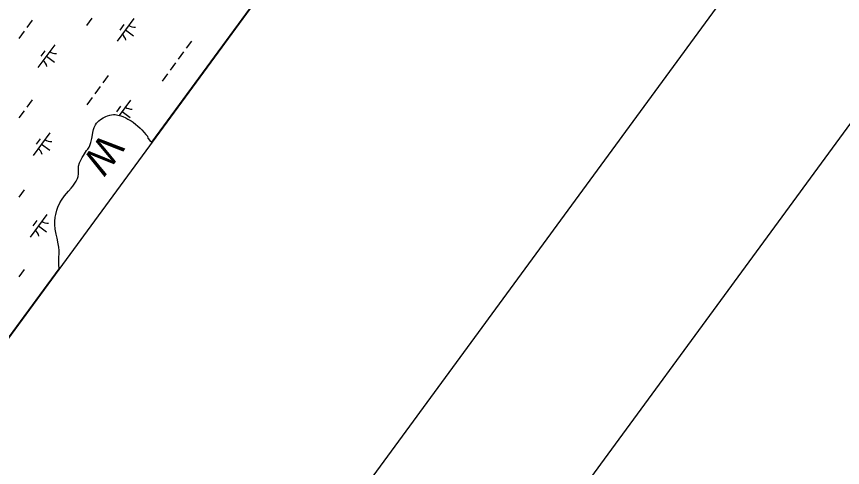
# Model space of a CAD drawing. Extents: x 3905714 to 3926767, y 183354 to 205755.
# Drawn here: x 3918098 to 3919561, y 188274 to 189073 of the extents above; entities that cross this region are included whole.
import ezdxf

# ---------------------------------------------------------------- set-up
doc = ezdxf.new("R2010")
doc.units = 0
for name, color, linetype in [('G-ANNO-NPLT', 7, 'Continuous'), ('V-ANNO-SYMB', 7, 'Continuous'), ('V-GRID-FRAM', 7, 'Continuous'), ('V-RIVR-IDEN', 7, 'Continuous'), ('V-TOPO-SHOR', 7, 'Continuous'), ('V-WETL-SWMP', 7, 'Continuous')]:
    doc.layers.add(name, color=color, linetype=linetype)

msp = doc.modelspace()

# ---------------------------------------------------------------- linework, layer by layer
at = {"layer": 'G-ANNO-NPLT'}
msp.add_lwpolyline([(3916784.5, 205519.9), (3905949.4, 190731), (3915696.7, 183589.7), (3926531.8, 198378.7)], close=True, dxfattribs=at)
at = {"layer": 'V-ANNO-SYMB'}
msp.add_lwpolyline([(3916223.9, 204226), (3906447.8, 190882.4), (3915690.8, 184110.5), (3925467, 197454.1), (3916223.9, 204226)], dxfattribs=at)
at = {"layer": 'V-GRID-FRAM'}
msp.add_lwpolyline([(3924287.8, 196971.1), (3915521.4, 185005.6), (3909313.3, 189695.8), (3918205.9, 201877.9), (3924287.8, 196971.1)], dxfattribs=at)
at = {"layer": 'V-TOPO-SHOR'}
msp.add_lwpolyline([(3918173.7, 188625.7), (3918173.1, 188633), (3918173.2, 188638), (3918173.6, 188646), (3918174, 188652.1), (3918174, 188658), (3918173.3, 188663.7), (3918172.4, 188670), (3918170.2, 188680.1), (3918168.8, 188686.8), (3918167, 188695.7), (3918166.4, 188704), (3918166.5, 188709.4), (3918167, 188717.3), (3918167.9, 188722), (3918169.9, 188729.7), (3918171.7, 188734.7), (3918175.2, 188742.4), (3918178.2, 188747.4), (3918183.2, 188755), (3918186.8, 188759.3), (3918190.2, 188763.3), (3918195.3, 188768.7), (3918198.2, 188772.2), (3918201.8, 188777.3), (3918204, 188780.7), (3918206.4, 188785.5), (3918207.3, 188788.9), (3918207.9, 188794.1), (3918208.3, 188799.8), (3918208.3, 188807.4), (3918210, 188813.4), (3918211.5, 188817), (3918214.8, 188822.6), (3918217, 188826.4), (3918220.8, 188832.2), (3918222.4, 188835.2), (3918224.5, 188837.7), (3918226.9, 188841.4), (3918228, 188844.2), (3918230.1, 188849.2), (3918231.8, 188856.7), (3918233.1, 188862.8), (3918233.8, 188866.9), (3918234.9, 188872.6), (3918235.9, 188876), (3918238.2, 188880.8), (3918240.3, 188883.6), (3918244.2, 188887.6), (3918247.1, 188890.3), (3918251.7, 188893.4), (3918256.3, 188895.6), (3918259.3, 188896.7), (3918263.8, 188897.9), (3918266.8, 188898.6), (3918270.1, 188899.1), (3918273.1, 188899), (3918277.9, 188897.8), (3918283.3, 188896.4), (3918286.8, 188895.3), (3918292.1, 188893), (3918295.8, 188891), (3918301.2, 188887.7), (3918304.9, 188885.4), (3918309.8, 188881.4), (3918312.9, 188878.8), (3918317.2, 188874.8), (3918320.1, 188871.7), (3918324.6, 188867), (3918327.6, 188863.6), (3918330.3, 188860.4), (3918331.2, 188857.2), (3918334.7, 188853.2), (3918337.9, 188849.9)], dxfattribs=at)
at = {"layer": 'V-WETL-SWMP'}
for p, q in [((3918337.9, 188849.9), (3919501.5, 190438.1)), ((3918126.3, 189066.2), (3918116.9, 189053.3)), ((3918231.7, 189069.5), (3918222.3, 189056.6)), ((3918305.9, 189069.2), (3918276.4, 189028.8)), ((3918288.5, 189058.4), (3918281.4, 189048.7)), ((3918291.2, 189049), (3918305.7, 189038.4)), ((3918112.1, 189046.8), (3918102.7, 189033.9)), ((3918166, 189022.6), (3918136.4, 188982.3)), ((3918408.5, 189029.3), (3918399, 189016.4)), ((3918148.5, 189011.9), (3918141.4, 189002.2)), ((3918394.3, 189009.9), (3918384.8, 188997)), ((3918151.2, 189002.5), (3918165.7, 188991.8)), ((3918380.1, 188990.5), (3918370.7, 188977.6)), ((3918260.5, 188967.9), (3918251.1, 188955)), ((3918365.9, 188971.2), (3918356.5, 188958.3)), ((3918246.3, 188948.5), (3918236.9, 188935.6)), ((3918126, 188925.1), (3918116.5, 188912.2)), ((3918232.1, 188929.2), (3918222.7, 188916.3)), ((3918300.2, 188924.3), (3918280.3, 188897.2)), ((3918111.8, 188905.8), (3918102.3, 188892.9)), ((3918282.7, 188913.6), (3918275.6, 188903.9)), ((3918285.4, 188904.2), (3918299.9, 188893.5)), ((3918244.2, 188887.6), (3918247.1, 188890.3)), ((3918247.1, 188890.3), (3918251.7, 188893.4)), ((3918251.7, 188893.4), (3918256.3, 188895.6)), ((3918256.3, 188895.6), (3918259.3, 188896.7)), ((3918259.3, 188896.7), (3918263.8, 188897.9)), ((3918263.8, 188897.9), (3918266.8, 188898.6)), ((3918266.8, 188898.6), (3918270.1, 188899.1)), ((3918270.1, 188899.1), (3918273.1, 188899)), ((3918273.1, 188899), (3918277.9, 188897.8)), ((3918277.9, 188897.8), (3918283.3, 188896.4)), ((3918283.3, 188896.4), (3918286.8, 188895.3)), ((3918286.8, 188895.3), (3918292.1, 188893)), ((3918292.1, 188893), (3918295.8, 188891)), ((3918295.8, 188891), (3918301.2, 188887.7)), ((3918301.2, 188887.7), (3918304.9, 188885.4)), ((3918234.9, 188872.6), (3918235.9, 188876)), ((3918235.9, 188876), (3918238.2, 188880.8)), ((3918238.2, 188880.8), (3918240.3, 188883.6)), ((3918240.3, 188883.6), (3918244.2, 188887.6)), ((3918304.9, 188885.4), (3918309.8, 188881.4)), ((3918309.8, 188881.4), (3918312.9, 188878.8)), ((3918312.9, 188878.8), (3918317.2, 188874.8)), ((3918317.2, 188874.8), (3918320.1, 188871.7)), ((3918157.6, 188866.7), (3918128.1, 188826.4)), ((3918231.8, 188856.7), (3918233.1, 188862.8)), ((3918233.1, 188862.8), (3918233.8, 188866.9)), ((3918233.8, 188866.9), (3918234.9, 188872.6)), ((3918320.1, 188871.7), (3918324.6, 188867)), ((3918324.6, 188867), (3918327.6, 188863.6)), ((3918327.6, 188863.6), (3918330.3, 188860.4)), ((3918330.3, 188860.4), (3918331.2, 188857.2)), ((3918140.2, 188856), (3918133.1, 188846.3)), ((3918142.8, 188846.6), (3918157.4, 188835.9)), ((3918226.9, 188841.4), (3918228, 188844.2)), ((3918228, 188844.2), (3918230.1, 188849.2)), ((3918230.1, 188849.2), (3918231.8, 188856.7)), ((3918331.2, 188857.2), (3918334.7, 188853.2)), ((3918334.7, 188853.2), (3918337.9, 188849.9)), ((3918217, 188826.4), (3918220.8, 188832.2)), ((3918220.8, 188832.2), (3918222.4, 188835.2)), ((3918222.4, 188835.2), (3918224.5, 188837.7)), ((3918224.5, 188837.7), (3918226.9, 188841.4)), ((3918210, 188813.4), (3918211.5, 188817)), ((3918211.5, 188817), (3918214.8, 188822.6)), ((3918214.8, 188822.6), (3918217, 188826.4)), ((3918207.9, 188794.1), (3918208.3, 188799.8)), ((3918208.3, 188807.4), (3918210, 188813.4)), ((3918208.3, 188799.8), (3918208.3, 188807.4)), ((3918204, 188780.7), (3918206.4, 188785.5)), ((3918206.4, 188785.5), (3918207.3, 188788.9)), ((3918207.3, 188788.9), (3918207.9, 188794.1)), ((3918195.3, 188768.7), (3918198.2, 188772.2)), ((3918198.2, 188772.2), (3918201.8, 188777.3)), ((3918201.8, 188777.3), (3918204, 188780.7)), ((3918112.2, 188765.4), (3918102.7, 188752.5)), ((3918183.2, 188755), (3918186.8, 188759.3)), ((3918186.8, 188759.3), (3918190.2, 188763.3)), ((3918190.2, 188763.3), (3918195.3, 188768.7)), ((3918171.7, 188734.7), (3918175.2, 188742.4)), ((3918175.2, 188742.4), (3918178.2, 188747.4)), ((3918178.2, 188747.4), (3918183.2, 188755)), ((3918167.9, 188722), (3918169.9, 188729.7)), ((3918169.9, 188729.7), (3918171.7, 188734.7)), ((3918151.8, 188721.9), (3918122.3, 188681.6)), ((3918166.5, 188709.4), (3918167, 188717.3)), ((3918167, 188717.3), (3918167.9, 188722)), ((3918134.4, 188711.1), (3918127.3, 188701.5)), ((3918137.1, 188701.7), (3918151.6, 188691.1)), ((3918166.4, 188704), (3918166.5, 188709.4)), ((3918167, 188695.7), (3918166.4, 188704)), ((3918168.8, 188686.8), (3918167, 188695.7)), ((3918170.2, 188680.1), (3918168.8, 188686.8)), ((3918172.4, 188670), (3918170.2, 188680.1)), ((3918173.3, 188663.7), (3918172.4, 188670)), ((3918174, 188658), (3918173.3, 188663.7)), ((3918174, 188652.1), (3918174, 188658)), ((3918173.2, 188638), (3918173.6, 188646)), ((3918173.6, 188646), (3918174, 188652.1)), ((3917936.7, 188302.3), (3918173.7, 188625.7)), ((3918111.8, 188624.4), (3918102.4, 188611.5)), ((3918173.1, 188633), (3918173.2, 188638)), ((3918173.7, 188625.7), (3918173.1, 188633))]:
    msp.add_line(p, q, dxfattribs=at)
for centre, start, end in [((3918307.7, 189071.1), 233, 274.5436), ((3918275, 189026.6), 13, 54.5436), ((3918167.7, 189024.6), 233, 274.5436), ((3918135.1, 188980.1), 13, 54.5436), ((3918301.9, 188926.3), 233, 274.5436), ((3918159.4, 188868.7), 233, 274.5436), ((3918126.7, 188824.1), 13, 54.5436), ((3918153.6, 188723.9), 233, 274.5436), ((3918120.9, 188679.3), 13, 54.5436)]:
    msp.add_arc(centre, 17.6, start, end, dxfattribs=at)

# ---------------------------------------------------------------- texts
at = {"layer": 'V-RIVR-IDEN'}
msp.add_text('W', height=50, rotation=233.8714, dxfattribs=at).set_placement((3918251.1, 188868.3))

doc.saveas('drawing.dxf')
